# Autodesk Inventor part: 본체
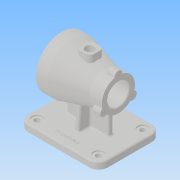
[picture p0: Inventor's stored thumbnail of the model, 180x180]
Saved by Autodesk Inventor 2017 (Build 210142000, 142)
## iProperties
Part Number: 본체
Material: 일반
Document SubType Name: Modeling
Designer: user
Density: 1 g/cm^3
Appearance: 기본값
Author: user
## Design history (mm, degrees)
sketch "스케치1"
  geometry: L1 (54, 55)-(-54, 55); L2 (-70, 39)-(-70, -39); L3 (-54, -55)-(54, -55); L4 (70, -39)-(70, 39); L5 (70, 55)-(-70, -55); L6 (-70, 55)-(70, -55); A1 r 16 centre (54, -39) between (54, -55) and (70, -39); A2 r 16 centre (54, 39) between (70, 39) and (54, 55); A3 r 16 centre (-54, 39) between (-54, 55) and (-70, 39); A4 r 16 centre (-54, -39) between (-70, -39) and (-54, -55); 1 further point
  constraints: 12 end point, 8 point on circle, 8 point on line, 8 tangent, 4 centre point, 3 equal radius, 2 midpoint, 2 parallel, 1 horizontal, 1 perpendicular
  dimensions: "d0" = 140 distance of L6.end L5.end; "d1" = 110 distance of L5.end L6.start; "d2" = 16 radius of A1
extrude "돌출1" new body sketch "스케치1" distance "d3" = 12; taper "d4" = 0 deg
sketch "스케치2"
  geometry: L1 (-84.655, 70)-(96.078, 70); L2 (-54, -12)-(54, -12) reference; L3 (-50, 70)-(-50, 115); L4 (-50, 115)-(-30, 115); L5 (-30, 115)-(27, 99); L6 (27, 99)-(50, 99); L7 (50, 99)-(50, 70); L8 (-70, 0)-(-70, -12) reference; 1 further point
  constraints: 12 end point, 2 perpendicular, 2 point on line, 1 horizontal, 1 parallel, 1 vertical
  dimensions: "d5" = 82 distance between parallel lines of L2 L1; "d6" = 20 distance of L3.end L4.end; "d7" = 100 distance between parallel lines of L7 L3; "d8" = 23 distance of L5.end L6.end; "d9" = 90 diameter of L4 L1; "d10" = 58 diameter of L6 L1; "d11" = 20 distance between parallel lines of L8 L3
revolve "회전1" sketch "스케치2" stored, may be unused: angle "d12" = 90 deg
sketch "스케치3"
  geometry: L1 (50, 41)-(50, 99) reference; L2 (-50, 25)-(-50, 115) reference; L3 (50, 70)-(-50, 70); L4 (-50, 101)-(-30, 101); L5 (-27, 98)-(-27, 98); L6 (-24, 95)-(17, 95); L7 (20, 92)-(20, 92); L8 (23, 89)-(50, 89); L9 (50, 70)-(50, 89); L10 (-50, 101)-(-50, 70); A1 r 3 centre (23, 92) between (20, 92) and (23, 89); A2 r 3 centre (17, 92) between (20, 92) and (17, 95); A3 r 3 centre (-24, 98) between (-27, 98) and (-24, 95); A4 r 3 centre (-30, 98) between (-27, 98) and (-30, 101); 3 further points
  constraints: 16 end point, 8 point on circle, 8 tangent, 6 perpendicular, 6 point on line, 4 centre point, 3 equal radius, 2 midpoint, 1 collinear
  dimensions: "d13" = 38 diameter of L8 L3; "d14" = 50 diameter of L6 L3; "d15" = 62 diameter of L4 L3; "d16" = 23 distance between parallel lines of L5 L2; "d17" = 47 distance of point (-27, 95) point (20, 95); "d18" = 3 radius of A1
revolve "회전2" sketch "스케치3" stored, may be unused: angle "d19" = 90 deg
fillet "모깎기1" dims "d20" = 3
sketch "스케치4"
  geometry: L1 (-37, -4)-(37, -4); L2 (37, -4)-(37, 4); L3 (37, 4)-(-37, 4); L4 (-37, 4)-(-37, -4); L5 (-37, -4)-(37, 4); L6 (37, -4)-(-37, 4); L7 (-4, -24)-(4, -24); L8 (4, -24)-(4, 24); L9 (4, 24)-(-4, 24); L10 (-4, 24)-(-4, -24); L11 (-4, -24)-(4, 24); L12 (4, -24)-(-4, 24); 1 further point
  constraints: 24 end point, 4 midpoint, 4 parallel, 2 horizontal, 2 perpendicular
  dimensions: "d21" = 74 distance of L3.end L2.end; "d22" = 8 distance of L2.end L1.end; "d23" = 8 distance of L9.end L8.end; "d24" = 48 distance of L8.end L7.end
extrude "돌출2" join sketch "스케치4" stored distance "d25" = 0; taper "d26" = 0 deg
node "작업 평면1"
sketch "스케치5"
  geometry: L1 (4.5, 12.5)-(-4.5, 12.5); L2 (-12.5, 4.5)-(-12.5, -4.5); L3 (-4.5, -12.5)-(4.5, -12.5); L4 (12.5, -4.5)-(12.5, 4.5); L5 (12.5, 12.5)-(-12.5, -12.5); L6 (-12.5, 12.5)-(12.5, -12.5); L7 (50, 45)-(50, -45) reference; L8 (-54, -55)-(54, -55) reference; A1 r 8 centre (4.5, -4.5) between (4.5, -12.5) and (12.5, -4.5); A2 r 8 centre (4.5, 4.5) between (12.5, 4.5) and (4.5, 12.5); A3 r 8 centre (-4.5, 4.5) between (-4.5, 12.5) and (-12.5, 4.5); A4 r 8 centre (-4.5, -4.5) between (-12.5, -4.5) and (-4.5, -12.5); 2 further points
  constraints: 12 end point, 8 point on circle, 8 point on line, 8 tangent, 4 centre point, 3 equal radius, 2 midpoint, 2 parallel, 1 horizontal, 1 perpendicular
  dimensions: "d28" = 25 distance of L6.end L5.end; "d29" = 25 distance of L5.end L6.start; "d31" = 50 distance from line of L7 point (0, 0); "d32" = 55 distance from line of point (0, 0) L8; "d33" = 8 radius of A1
extrude "돌출3" join sketch "스케치5" stored distance "d34" = 12; taper "d35" = 0 deg
sketch "스케치6"
  geometry: C1 r 7.5 at (0, 0); 1 further point
  constraints: 1 centre point, 1 coincident
  dimensions: "d36" = 15 diameter of C1
extrude "돌출4" cut sketch "스케치6" stored distance "d37" = 12; taper "d38" = 0 deg
feature "면 기울기1" dims angle "d39" = 5 deg
feature "면 기울기2" dims angle "d40" = 5 deg
fillet "모깎기2" dims "d41" = 3
sketch "스케치7"
  geometry: L1 (0, 0)-(0, 29); L2 (0, 0)-(-25.115, -14.5); L3 (0, 0)-(25.115, -14.5); C1 r 7 at (0, 29); C2 r 7 at (25.115, -14.5); C3 r 7 at (-25.115, -14.5); A1 r 29 centre (0, 0) between (0, 29) and (-25.115, -14.5) reference; 1 further point
  constraints: 6 end point, 3 centre point, 3 coincident, 3 point on circle, 1 vertical
  dimensions: "d42" = 120 deg angle of L3 L1; "d43" = 120 deg angle of L3 L2; "d44" = 14 diameter of C1; "d45" = 14 diameter of C2; "d46" = 14 diameter of C3
extrude "돌출5" join sketch "스케치7" distance "d47" = 15; taper "d48" = 0 deg
fillet "모깎기3" dims "d49" = 3, "d50" = 1
sketch "스케치8" dims "d51" = 80
  geometry: L1 (34.641, -20)-(-34.641, 20); L2 (0, 0)-(40, 0); L3 (-34.641, -20)-(34.641, 20); L4 (0, 0)-(40, 0); L5 (0, -40)-(0, 40); C1 r 45 at (0, 0) reference; 7 further points
  constraints: 10 end point, 5 coincident, 3 midpoint, 2 horizontal, 1 perpendicular, 10 other
  dimensions: "d52" = 150 deg angle of L2 L1; "d53" = 30 deg angle of L4 L3
hole "구멍1" sketch "스케치8" at (0, 40), (34.641, 20), (34.641, -20), (0, -40), (-34.641, -20), (-34.641, 20) diameter "d54" = 3.242; stored, may be unused: countersink angle "d58" = 82 deg, drill point angle "d60" = 118 deg; dims "d55" = 9, "d56" = 3.023, "d57" = 2, "d59" = 11
sketch "스케치9"
  geometry: A1 r 7 centre (25.115, -43.5) between (21.55, -49.524) and (28.549, -37.4) reference; A2 r 7 centre (0, 0) between (7, -0.075) and (-7, -0.075) reference; A3 r 7 centre (-25.115, -43.5) between (-28.549, -37.4) and (-21.55, -49.524) reference; 4 further points
  constraints: 3 coincident
hole "구멍2" sketch "스케치9" at (0, 0), (25.115, -43.5), (-25.115, -43.5) diameter "d61" = 3.242; stored, may be unused: countersink angle "d65" = 82 deg, drill point angle "d67" = 118 deg; dims "d62" = 9, "d63" = 3.023, "d64" = 2, "d66" = 11
chamfer "모따기1" distance "d68" = 1; stored, may be unused: second distance "d69" = 2, angle "d70" = 45 deg
sketch "스케치10"
  geometry: A1 r 13 centre (-54, -39) between (-67, -39) and (-54, -52) reference; A2 r 13 centre (54, -39) between (54, -52) and (67, -39) reference; A3 r 13 centre (54, 39) between (67, 39) and (54, 52) reference; A4 r 13 centre (-54, 39) between (-54, 52) and (-67, 39) reference; 5 further points
  constraints: 4 coincident
hole "구멍3" sketch "스케치10" at (54, 39), (54, -39), (-54, -39), (-54, 39) diameter "d71" = 9; stored, may be unused: countersink angle "d75" = 82 deg, drill point angle "d77" = 118 deg; dims "d72" = 9, "d73" = 18, "d74" = 2, "d76" = 12
sketch "스케치11"
  geometry: L1 (-70, 39)-(-70, -39) reference; L2 (-54, -55)-(54, -55) reference; 2 further points
  constraints: 1 other
  dimensions: "d78" = 70 distance from line of L1 point (0, -40); "d79" = 15 distance from line of L2 point (0, -40)
feature "엠보싱1" sketch "스케치11" dims "d0" = 140, "d1" = 110, "d2" = 16, "d80" = 0.5, "d81" = 0
node "솔리드1"
other parameters: "d27" = -127
